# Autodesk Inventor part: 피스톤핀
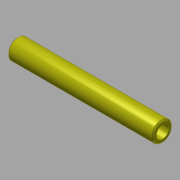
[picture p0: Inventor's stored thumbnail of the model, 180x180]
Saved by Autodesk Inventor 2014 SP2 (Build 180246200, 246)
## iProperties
Created: 2016-11
Part Number: 피스톤핀
Material: 강철, 탄소
Document SubType Name: Modeling
Designer: mduedu
Density: 7.87 g/cm^3
Mass: 13.9342 g
Surface Area: 24.1465 cm^2
Volume: 1.77055 cm^3
Appearance: 노란색
Author: mduedu
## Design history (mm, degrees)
sketch "스케치1"
  geometry: C1 r 2.5 at (0, 0); C2 r 4 at (0, 0); 1 further point
  constraints: 2 centre point, 2 coincident
  dimensions: "d0" = 5 diameter of C1; "d1" = 8 diameter of C2
extrude "돌출1" new body sketch "스케치1" stored distance "d2" = 58; taper "d3" = 0 deg
chamfer "모따기1" distance "d4" = 0.5; stored, may be unused: second distance "d5" = 2, angle "d6" = 45 deg
node "솔리드1"
